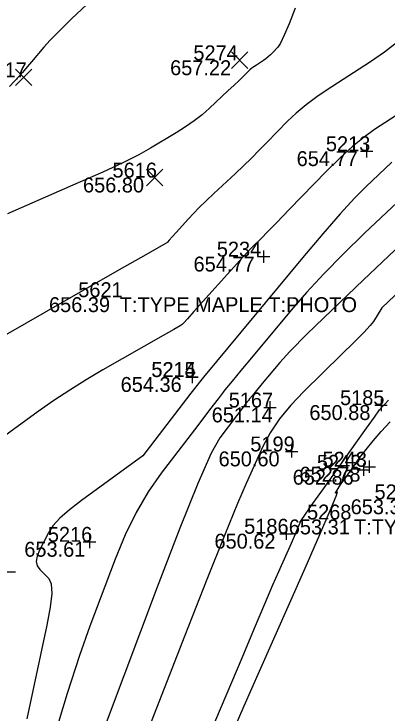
# Model space of a CAD drawing. Extents: x 2129350 to 2137777, y 657588 to 659885.
# Drawn here: x 2132788.2 to 2132818.3, y 658327.6 to 658383.9 of the extents above; entities that cross this region are included whole.
import ezdxf

# ---------------------------------------------------------------- set-up
doc = ezdxf.new("R2010")
doc.units = 0
for name, color, linetype in [('DT_X_Contour_Major', 7, 'Continuous'), ('DT_X_Contour_Minor', 7, 'Continuous'), ('SV_X_Random_Point', 7, 'Continuous'), ('SV_X_Shot_Marker', 7, 'Continuous'), ('SV_X_Text_Comment', 7, 'Continuous'), ('SV_X_Text_Elevation', 7, 'Continuous'), ('SV_X_Text_Name', 7, 'Continuous')]:
    doc.layers.add(name, color=color, linetype=linetype)

msp = doc.modelspace()

# ---------------------------------------------------------------- linework, layer by layer
at = {"layer": 'DT_X_Contour_Major'}
msp.add_lwpolyline([(2132820.987, 658377.055), (2132817.223, 658374.618), (2132816.377, 658374.017), (2132815.451, 658373.256), (2132814.446, 658372.337), (2132813.36, 658371.258), (2132810.361, 658368.171), (2132809.361, 658367.144), (2132808.613, 658366.378), (2132808.116, 658365.873), (2132807.869, 658365.63), (2132807.548, 658365.329), (2132807.338, 658365.114), (2132806.95, 658364.696), (2132806.383, 658364.075), (2132805.639, 658363.25), (2132803.415, 658360.778), (2132802.686, 658359.967), (2132802.165, 658359.387), (2132801.852, 658359.039), (2132801.748, 658358.922), (2132801.747, 658358.918), (2132801.576, 658358.819), (2132801.063, 658358.525), (2132800.208, 658358.036), (2132795.364, 658355.265), (2132794.013, 658354.469), (2132792.696, 658353.644), (2132791.413, 658352.79), (2132790.163, 658351.908), (2132786.876, 658349.517)], dxfattribs=at)
at = {"layer": 'DT_X_Contour_Minor'}
for points in [[(2132810.83, 658384.386), (2132810.336, 658383.145), (2132809.939, 658382.21), (2132809.638, 658381.58), (2132809.432, 658381.255), (2132809.011, 658380.796), (2132808.846, 658380.628), (2132808.668, 658380.469), (2132808.477, 658380.319), (2132808.272, 658380.178), (2132807.709, 658379.813), (2132807.51, 658379.679), (2132807.336, 658379.551), (2132807.187, 658379.427), (2132807.063, 658379.309), (2132806.764, 658379.002), (2132806.597, 658378.836), (2132806.317, 658378.568), (2132805.925, 658378.198), (2132805.422, 658377.727), (2132803.931, 658376.333), (2132803.345, 658375.818), (2132802.706, 658375.317), (2132802.014, 658374.83), (2132801.268, 658374.357), (2132799.209, 658373.117), (2132798.266, 658372.593), (2132796.981, 658371.953), (2132795.355, 658371.196), (2132793.388, 658370.323), (2132787.686, 658367.838)], [(2132794.087, 658384.692), (2132792.854, 658383.524), (2132791.865, 658382.562), (2132791.121, 658381.806), (2132790.622, 658381.256), (2132789.617, 658380.065), (2132789.286, 658379.672), (2132789.044, 658379.386), (2132788.893, 658379.208), (2132788.832, 658379.137), (2132788.791, 658379.092), (2132788.769, 658379.068), (2132788.736, 658379.032), (2132788.692, 658378.984), (2132788.636, 658378.924), (2132788.473, 658378.746), (2132788.416, 658378.684), (2132788.369, 658378.632), (2132788.332, 658378.591), (2132788.304, 658378.559), (2132788.242, 658378.488), (2132787.856, 658378.098)], [(2132819.081, 658381.692), (2132818.025, 658380.863), (2132816.894, 658380.083), (2132813.783, 658378.068), (2132812.684, 658377.327), (2132811.723, 658376.616), (2132810.899, 658375.935), (2132810.212, 658375.284), (2132808.563, 658373.586), (2132807.94, 658372.953), (2132807.309, 658372.327), (2132806.669, 658371.707), (2132806.021, 658371.094), (2132804.282, 658369.469), (2132803.665, 658368.884), (2132803.119, 658368.349), (2132802.643, 658367.864), (2132802.239, 658367.429), (2132801.253, 658366.333), (2132800.93, 658365.974), (2132800.699, 658365.717), (2132800.56, 658365.562), (2132800.514, 658365.51), (2132800.514, 658365.509), (2132800.089, 658365.265), (2132798.814, 658364.536), (2132796.69, 658363.321), (2132793.716, 658361.62), (2132784.652, 658356.437)], [(2132818.609, 658372), (2132816.51, 658370.008), (2132815.602, 658369.09), (2132814.452, 658367.831), (2132813.06, 658366.23), (2132811.426, 658364.287), (2132803.456, 658354.685), (2132803.237, 658354.42), (2132803.236, 658354.418), (2132802.452, 658353.391), (2132798.591, 658348.338), (2132793.638, 658344.736), (2132792.676, 658343.995), (2132791.913, 658343.317), (2132791.349, 658342.702), (2132790.983, 658342.149), (2132790.274, 658340.758), (2132790.075, 658340.268), (2132790.011, 658339.842), (2132790.082, 658339.48), (2132790.289, 658339.181), (2132791.018, 658338.469), (2132791.214, 658338.034), (2132791.255, 658337.261), (2132791.141, 658336.152), (2132790.872, 658334.705), (2132789.254, 658327.167)], [(2132821.254, 658370.853), (2132816.419, 658366.265), (2132814.689, 658364.588), (2132813.128, 658362.997), (2132811.734, 658361.493), (2132810.509, 658360.075), (2132807.466, 658356.409), (2132806.467, 658355.206), (2132805.754, 658354.346), (2132805.183, 658353.658), (2132805.183, 658353.657), (2132805.046, 658353.477), (2132804.635, 658352.938), (2132803.949, 658352.041), (2132802.99, 658350.786), (2132800.066, 658346.959), (2132799.011, 658345.45), (2132798.041, 658343.793), (2132797.154, 658341.989), (2132796.351, 658340.037), (2132794.322, 658334.635), (2132793.488, 658332.267), (2132792.508, 658329.215), (2132791.381, 658325.479)], [(2132829.332, 658371.204), (2132817.793, 658360.256), (2132817.13, 658359.174), (2132816.864, 658358.832), (2132816.348, 658358.272), (2132815.583, 658357.492), (2132814.569, 658356.494), (2132811.533, 658353.539), (2132810.473, 658352.43), (2132809.57, 658351.319), (2132808.825, 658350.205), (2132808.237, 658349.088), (2132806.88, 658346.107), (2132806.191, 658344.505), (2132805.143, 658341.934), (2132803.736, 658338.396), (2132801.969, 658333.889), (2132796.779, 658320.58)], [(2132823.9, 658369.706), (2132816.327, 658362.522), (2132813.776, 658360.085), (2132811.804, 658358.163), (2132810.409, 658356.755), (2132809.592, 658355.862), (2132808.185, 658354.167), (2132807.724, 658353.611), (2132807.394, 658353.214), (2132807.196, 658352.975), (2132807.13, 658352.896), (2132807.13, 658352.895), (2132807.066, 658352.812), (2132806.876, 658352.563), (2132806.559, 658352.148), (2132806.116, 658351.568), (2132804.764, 658349.798), (2132804.069, 658348.549), (2132802.998, 658346.127), (2132801.552, 658342.533), (2132799.729, 658337.766), (2132794.369, 658323.493)], [(2132803.631, 658325.118), (2132806.561, 658332.082), (2132807.57, 658334.474), (2132808.398, 658336.428), (2132809.047, 658337.944), (2132809.515, 658339.021), (2132810.524, 658341.308), (2132810.853, 658342.057), (2132811.083, 658342.589), (2132811.214, 658342.904), (2132811.246, 658343.002), (2132811.198, 658342.972), (2132811.305, 658343.134), (2132811.658, 658343.643), (2132812.26, 658344.498), (2132813.11, 658345.7), (2132815.705, 658349.366), (2132816.567, 658350.579), (2132817.206, 658351.47), (2132817.623, 658352.039), (2132817.816, 658352.285), (2132818.035, 658352.511), (2132818.344, 658352.838)], [(2132805.787, 658326.041), (2132806.741, 658328.212), (2132807.973, 658331.009), (2132811.63, 658339.301), (2132812.822, 658342.016), (2132813.655, 658343.944), (2132814.129, 658345.085), (2132814.245, 658345.439), (2132814.073, 658345.332), (2132814.073, 658345.376), (2132814.202, 658345.589), (2132814.458, 658345.97), (2132814.843, 658346.52), (2132816.041, 658348.212), (2132816.531, 658348.867), (2132817.1, 658349.562), (2132817.751, 658350.298), (2132818.481, 658351.074)]]:
    msp.add_lwpolyline(points, dxfattribs=at)
at = {"layer": 'SV_X_Random_Point'}
for p, q in [((2132805.7, 658379.531), (2132807.034, 658380.867)), ((2132805.7, 658380.867), (2132807.034, 658379.531)), ((2132788.327, 658378.161), (2132789.661, 658379.497)), ((2132788.327, 658379.497), (2132789.661, 658378.161)), ((2132798.865, 658370.088), (2132800.199, 658371.422)), ((2132798.865, 658371.422), (2132800.199, 658370.088))]:
    msp.add_line(p, q, dxfattribs=at)
at = {"layer": 'SV_X_Shot_Marker'}
for p, q in [((2132816.58, 658373.379), (2132816.58, 658372.379)), ((2132816.08, 658372.879), (2132817.08, 658372.879)), ((2132816.58, 658372.879), (2132816.58, 658372.879)), ((2132808.289, 658364.889), (2132808.289, 658363.889)), ((2132807.789, 658364.389), (2132808.789, 658364.389)), ((2132808.289, 658364.389), (2132808.289, 658364.389)), ((2132802.537, 658355.19), (2132802.537, 658354.19)), ((2132802.54, 658355.195), (2132802.54, 658354.195)), ((2132802.037, 658354.69), (2132803.037, 658354.69)), ((2132802.04, 658354.695), (2132803.04, 658354.695)), ((2132802.537, 658354.69), (2132802.537, 658354.69)), ((2132802.54, 658354.695), (2132802.54, 658354.695)), ((2132817.737, 658352.929), (2132817.737, 658351.929)), ((2132808.804, 658352.74), (2132808.804, 658351.74)), ((2132817.237, 658352.429), (2132818.237, 658352.429)), ((2132817.737, 658352.429), (2132817.737, 658352.429)), ((2132808.304, 658352.24), (2132809.304, 658352.24)), ((2132808.804, 658352.24), (2132808.804, 658352.24)), ((2132810.548, 658349.199), (2132810.548, 658348.199)), ((2132810.048, 658348.699), (2132811.048, 658348.699)), ((2132810.548, 658348.699), (2132810.548, 658348.699)), ((2132816.788, 658347.968), (2132816.788, 658346.968)), ((2132815.829, 658347.224), (2132816.829, 658347.224)), ((2132816.288, 658347.468), (2132817.288, 658347.468)), ((2132816.329, 658347.724), (2132816.329, 658346.724)), ((2132816.329, 658347.224), (2132816.329, 658347.224)), ((2132816.788, 658347.468), (2132816.788, 658347.468)), ((2132810.103, 658342.573), (2132810.103, 658341.573)), ((2132794.294, 658341.92), (2132794.294, 658340.92)), ((2132809.603, 658342.073), (2132810.603, 658342.073)), ((2132810.103, 658342.073), (2132810.103, 658342.073)), ((2132793.794, 658341.42), (2132794.794, 658341.42)), ((2132794.294, 658341.42), (2132794.294, 658341.42)), ((2132787.332, 658339), (2132788.332, 658339))]:
    msp.add_line(p, q, dxfattribs=at)

# ---------------------------------------------------------------- texts
at = {"layer": 'SV_X_Text_Comment'}
for p in [(2132796.724, 658359.921), (2132815.563, 658342.02)]:
    msp.add_text('T:TYPE MAPLE T:PHOTO', height=1.2, dxfattribs=at).set_placement(p)
at = {"layer": 'SV_X_Text_Elevation'}
for s, p in [('657.22', (2132800.774, 658378.999)), ('654.77', (2132810.949, 658371.679)), ('656.80', (2132793.769, 658369.555)), ('654.77', (2132802.658, 658363.189)), ('656.39', (2132791.036, 658359.921)), ('654.36', (2132796.793, 658353.49)), ('654.36', (2132796.796, 658353.495)), ('651.14', (2132804.119, 658351.04)), ('650.88', (2132811.974, 658351.229)), ('650.60', (2132804.671, 658347.499)), ('652.86', (2132810.632, 658346.024)), ('652.78', (2132811.176, 658346.268)), ('653.38', (2132815.295, 658343.642)), ('653.31', (2132810.318, 658342.02)), ('650.62', (2132804.34, 658340.873)), ('653.61', (2132789.049, 658340.22))]:
    msp.add_text(s, height=1.2, dxfattribs=at).set_placement(p)
at = {"layer": 'SV_X_Text_Name'}
for s, p in [('5274', (2132802.644, 658380.199)), ('5617', (2132785.678, 658378.829)), ('5213', (2132813.302, 658372.879)), ('5616', (2132796.141, 658370.755)), ('5234', (2132804.529, 658364.389)), ('5621', (2132793.388, 658361.121)), ('5215', (2132799.259, 658354.69)), ('5214', (2132799.271, 658354.695)), ('5167', (2132805.488, 658352.24)), ('5185', (2132814.44, 658352.429)), ('5199', (2132807.223, 658348.699)), ('5242', (2132812.578, 658347.224)), ('5243', (2132813.028, 658347.468)), ('5267', (2132817.213, 658344.842)), ('5268', (2132811.784, 658343.22)), ('5186', (2132806.731, 658342.073)), ('5216', (2132790.941, 658341.42))]:
    msp.add_text(s, height=1.2, dxfattribs=at).set_placement(p)

doc.saveas('drawing.dxf')
